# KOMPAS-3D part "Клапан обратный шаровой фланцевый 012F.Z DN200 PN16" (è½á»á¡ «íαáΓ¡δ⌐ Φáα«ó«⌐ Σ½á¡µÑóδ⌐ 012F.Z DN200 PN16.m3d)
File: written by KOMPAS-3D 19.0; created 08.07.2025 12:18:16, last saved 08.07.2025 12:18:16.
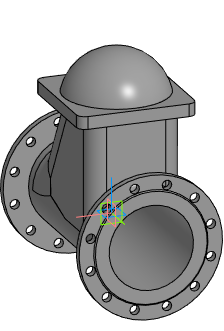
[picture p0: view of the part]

Document properties: Полное имя файла: E:\Dendor Работа Сачек\3D для проектировщиков\5.3 Тип 012F, 012F.Z Клапан обратный шаровой фланцевый\stp_Клапан обратный шаровой фланцевый 012F.Z PN10_16\Клапан обратный шаровой фланцевый 012F.Z DN200 PN16.m3d

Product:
- Part/product: Клапан обратный шаровой фланцевый 012F.Z DN200 PN16

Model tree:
1. Операция без истории:1  (labels: Клапан обратный шаровой фланцевый 012F.Z DN200 PN16)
